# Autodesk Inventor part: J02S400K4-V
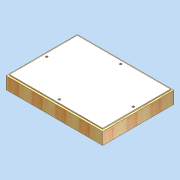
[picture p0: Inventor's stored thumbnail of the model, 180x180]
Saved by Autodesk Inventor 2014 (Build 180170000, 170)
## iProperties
Created: 2011-04
Part Number: J02S400K4-V
Document SubType Name: Modeling
Designer: david.appleford
Density: 0.467329 g/cm^3
Description: Joist 0.5w x 400mm - Locks 4
Mass: 8000 g
Surface Area: 5846.42 cm^2
Volume: 17118.6 cm^3
Cost Center: £40.00
Material: 000 Redwood
Appearance: Wood (Pine)
Justset: False
Title: Joist 0.5w x 400mm - Locks 4
Author: david.appleford
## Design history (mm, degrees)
sketch "Sketch1"
  geometry: L1 (0, 0)-(610, 0); L2 (610, 0)-(610, 468); L3 (610, 468)-(0, 468); L4 (0, 468)-(0, 0); L5 (34, 434)-(576, 434); L6 (576, 434)-(576, 34); L7 (576, 34)-(34, 34); L8 (34, 34)-(34, 434)
  constraints: 16 end point, 4 parallel, 2 perpendicular, 1 horizontal, 3 other
  dimensions: "d0" = 610 distance between parallel lines of L2 L4 (= 0.5 x w); "d1" = 468 distance between parallel lines of L1 L3; "d2" = 34 distance between parallel lines of L5 L3 (= 0.5 x t); "d30" = 400 distance between parallel lines of L7 L5 (derived); "d31" = 542 distance between parallel lines of L6 L8 (derived)
extrude "Extrusion1" new body sketch "Sketch1" distance "d3" = 68 (= t); taper "d4" = 0 deg
sketch "Sketch2"
  geometry: L1 (576, 434)-(576, 34) reference; L2 (34, 434)-(576, 434) reference; L3 (34, 34)-(34, 434) reference; L4 (576, 34)-(34, 34) reference; L5 (566, 424)-(566, 44); L6 (566, 44)-(44, 44); L7 (44, 44)-(44, 424); L8 (44, 424)-(566, 424); 1 further point
  constraints: 8 end point, 3 other
  dimensions: "d5" = 10 distance between parallel lines of L8 L2
extrude "Extrusion2" join sketch "Sketch2" distance "d6" = 6 (= sw); taper "d7" = 0 deg
sketch "Sketch3"
  geometry: L1 (-44, 424)-(-566, 424) reference; L2 (-566, 424)-(-566, 44) reference; L3 (-44, 44)-(-44, 424) reference; L4 (-566, 44)-(-44, 44) reference; 1 further point
extrude "Extrusion3" join sketch "Sketch3" distance "d8" = 6 (= sw); taper "d9" = 0 deg
sketch "Sketch4"
  geometry: L1 (34, 434)-(576, 434) reference; L2 (576, 434)-(576, 34) reference; L3 (576, 34)-(34, 34) reference; L4 (34, 34)-(34, 434) reference; 5 further points
  constraints: 1 horizontal alignment, 1 vertical alignment
  dimensions: "d10" = 28 distance from line of point (305, 406) L1 (= k); "d13" = 28 distance from line of point (62, 234) L4 (= k); "d14" = 305 horizontal distance of point (305, 406) point (0, 0) (= 0.25 x w); "d29" = 28 distance from line of L2 point (548, 234) (= d13); "d32" = 400 distance between parallel lines of L3 L1 (derived); "d33" = 200 distance from line of L1 point (62, 234) (= 0.5 x d32); "d34" = 28 distance from line of point (305, 62) L3
hole "Hole1" sketch "Sketch4" at (305, 406), (62, 234), (548, 234), (305, 62) diameter "d22" = 12 (= hd); stored, may be unused: countersink angle "d26" = 90 deg, drill point angle "d28" = 118 deg; dims "d23" = 6, "d24" = 4, "d25" = 2, "d27" = 8
body "Solid1"
node "Projected Loop1"
other parameters: "t" = 68 [user parameter; used in 2 equation terms], "e" = 16 [user parameter], "sw" = 6 [user parameter; used in 2 equation terms], "sc" = 9 [user parameter], "sf" = 12 [user parameter], "k" = 28 [user parameter; used in 2 equation terms], "hd" = 12 [user parameter; used in 1 equation term]
